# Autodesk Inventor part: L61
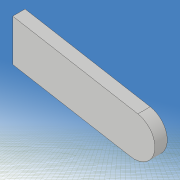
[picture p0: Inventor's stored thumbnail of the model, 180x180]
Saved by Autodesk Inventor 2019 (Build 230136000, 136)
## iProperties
Created: 2021-05
Part Number: L61
Material: 一般
Document SubType Name: Modeling
Designer: kikut
Density: 1 g/cm^3
Appearance: 既定
Mass: 0.00934248 g
Surface Area: 0.426451 cm^2
Volume: 0.00934248 cm^3
Author: kikut
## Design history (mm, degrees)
sketch "スケッチ1"
  geometry: L1 (80, 60)-(-80, 60); L2 (-80, 60)-(-80, -60); L3 (-80, -60)-(80, -60); L4 (80, -60)-(80, 60); L5 (80, 60)-(-80, -60); L6 (-80, 60)-(80, -60); 1 further point
  constraints: 12 end point, 2 midpoint, 2 parallel, 1 horizontal, 1 perpendicular
  dimensions: "d0" = 160 distance of L2.end L3.end; "d1" = 120 distance of L1.end L2.end
extrude "押し出し1" new body sketch "スケッチ1" stored distance "d2" = 0.6; taper "d3" = 0 deg
sketch "スケッチ2"
  geometry: L1 (-140, 0)-(140, 0) reference; L2 (0, -54)-(20, -30); L3 (0, 54)-(20, 30); L4 (0, -3)-(6.514, -3); L5 (6.514, -3)-(16, -6); L6 (16, -6)-(24, -3); L7 (24, -3)-(33.716, -3); L8 (0, 3)-(6.514, 3); L9 (6.514, 3)-(16, 6); L10 (16, 6)-(24, 3); L11 (24, 3)-(33.716, 3); L12 (0, -98)-(0, 98) reference; L13 (-100, -70)-(100, -70); L14 (100, -70)-(100, 70); L15 (100, 70)-(-100, 70); L16 (-100, 70)-(-100, -70); L17 (-100, -70)-(100, 70); L18 (100, -70)-(-100, 70); A1 r 60 centre (54.312, 28.5) between (0, 54) and (0, 3); A2 r 60 centre (54.312, -28.5) between (0, -3) and (0, -54); A3 r 18.111 centre (18, -12) between (20, -30) and (33.716, -3); A4 r 18.111 centre (18, 12) between (33.716, 3) and (20, 30); 1 further point
  constraints: 32 end point, 8 point on circle, 8 symmetric about line, 4 centre point, 3 horizontal, 2 collinear, 2 midpoint, 2 parallel, 1 perpendicular
  dimensions: "d5" = 60 radius of A1; "d6" = 6 distance of L8.start L4.start; "d7" = 108 distance of L3.start L2.start; "d8" = 0 horizontal distance of L3.start L8.start; "d9" = 60 distance of L3.end L2.end; "d10" = 0 horizontal distance of point (0, 0) L3.start; "d11" = 20 horizontal distance of L3.start L3.end; "d12" = 24 distance of A4.centre A3.centre; "d13" = 6 distance of L11.end L7.end; "d14" = 12 distance of L9.end L5.end; "d15" = 16 distance from line of L12 L5.end; "d16" = 24 distance from line of L6.end L12; "d17" = 200 distance of L14.end L15.end; "d18" = 140 distance of L15.end L13.start; "d30" = 18 distance from line of L12 A4.centre
extrude "押し出し2" cut sketch "スケッチ2" stored distance "d19" = 10; taper "d20" = 0 deg
sketch "スケッチ3"
  geometry: L1 (49.705, -17.97)-(33.948, -15.191); L2 (33.948, -15.191)-(34.295, -13.222); L3 (34.295, -13.222)-(50.052, -16); L4 (50.052, -16)-(49.705, -17.97); L5 (49.705, -17.97)-(34.295, -13.222); L6 (33.948, -15.191)-(50.052, -16); L7 (50.052, 16)-(34.295, 13.222); L8 (34.295, 13.222)-(33.948, 15.191); L9 (33.948, 15.191)-(49.705, 17.97); L10 (49.705, 17.97)-(50.052, 16); L11 (50.052, 16)-(33.948, 15.191); L12 (34.295, 13.222)-(49.705, 17.97); L13 (-112, 0)-(112, 0) reference; L14 (0, -84)-(0, 84) reference; 3 further points
  constraints: 24 end point, 4 midpoint, 4 parallel, 2 perpendicular, 2 symmetric about line
  dimensions: "d21" = 2 distance of L3.end L1.start; "d22" = 2 distance of L9.end L7.start; "d23" = 16 distance of L8.end L9.end; "d24" = 42 distance from line of L14 point (42, 15.596); "d26" = 10 deg angle of L7 L13; "d62" = 16 distance from line of L3.end L13
extrude "押し出し3" join sketch "スケッチ3" distance "d27" = 0.6; taper "d28" = 0 deg
fillet "フィレット1" dims "d31" = 2
fillet "フィレット2" dims "d32" = 1
sketch "スケッチ7"
  geometry: L1 (-20, 60)-(80, 60); L2 (80, 60)-(80, -60); L3 (80, -60)-(-20, -60); L4 (-20, -60)-(-20, 60); L5 (0, -82.207)-(0, 85.793) reference; L6 (-40, 0)-(100, 0) reference; L7 (43, -10)-(55, -10); L8 (55, -10)-(55, -20); L9 (55, -20)-(43, -20); L10 (43, -20)-(43, -10); 1 further point
  constraints: 16 end point, 4 parallel, 2 horizontal, 2 perpendicular, 1 other
  dimensions: "d80" = 120 distance of L3.end L1.start; "d81" = 20 distance between parallel lines of L5 L4; "d82" = 100 distance of L1.start L1.end; "d84" = 12 distance of L8.end L9.end; "d85" = 10 distance of L7.end L8.end; "d86" = 63 distance between parallel lines of L4 L10; "d93" = 40 distance between parallel lines of L3 L9
extrude "押し出し5" cut sketch "スケッチ7" stored distance "d87" = 10; taper "d88" = 0 deg
node "ソリッド1"
